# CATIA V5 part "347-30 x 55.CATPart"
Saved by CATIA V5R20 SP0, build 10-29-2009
Part number: 347-30 x 55
Definition: NONE
Nomenclature: 347-30 x 55
Source: Unknown
Description: 347-30 x 55
Bounding box of the stored display mesh (mm): x 0 to 55, y -22.5 to 22.5, z -22.5 to 22.5
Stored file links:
  C:\Users\Utente\Desktop\IO LAVORO\3D X SITO CF\X SITO\3D files 347\347-30 x 55.CATPart
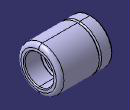
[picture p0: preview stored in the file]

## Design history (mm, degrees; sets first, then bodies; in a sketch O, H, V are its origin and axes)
Body1 "347-30 x 55" (main body)
  Solid1: solid without history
